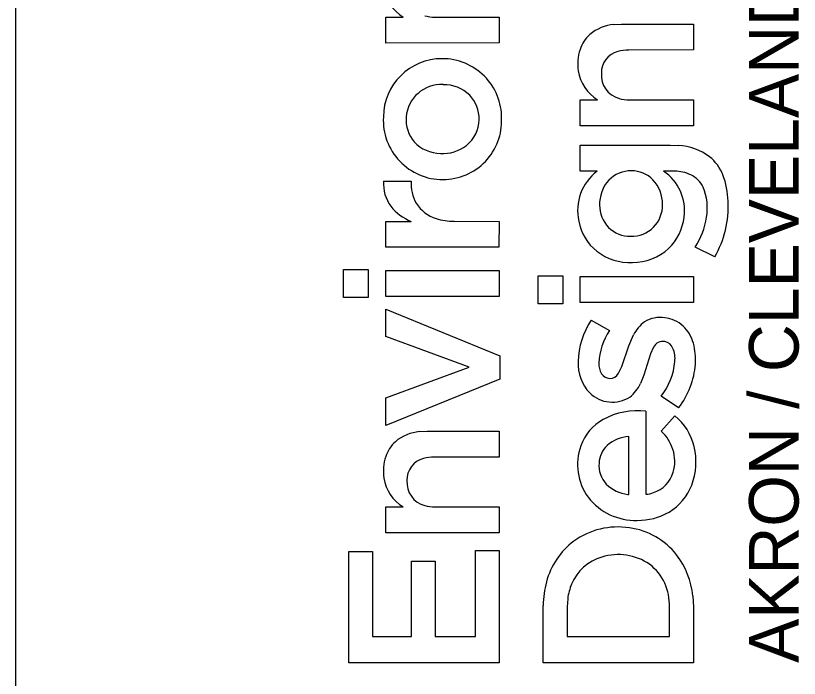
# Model space of a CAD drawing. Extents: x -0.2 to 34, y 0 to 22.
# Drawn here: x 32 to 32.901, y 3.12 to 3.882 of the extents above; entities that cross this region are included whole.
import ezdxf

# ---------------------------------------------------------------- set-up
doc = ezdxf.new("R2010")
doc.units = 0
doc.layers.add('DV_X_Property_Line', color=7, linetype='Continuous')
doc.layers.add('RW_X_Esmt_SH', color=7, linetype='Continuous')

msp = doc.modelspace()

# ---------------------------------------------------------------- linework, layer by layer
at = {"layer": 'DV_X_Property_Line'}
msp.add_line((32, 0.5), (32, 21.5), dxfattribs=at)
at = {"layer": 'RW_X_Esmt_SH'}
for p, q in [((32.42542, 3.88066), (32.44552, 3.88071)), ((32.42542, 3.85086), (32.42542, 3.88066)), ((32.48222, 3.88071), (32.55569, 3.88071)), ((32.55569, 3.88071), (32.55571, 3.85096)), ((32.68784, 3.8722), (32.69634, 3.87266)), ((32.69634, 3.87266), (32.77916, 3.87266)), ((32.77916, 3.87266), (32.77917, 3.84287)), ((32.55571, 3.85096), (32.42542, 3.85086)), ((32.77917, 3.84287), (32.70485, 3.8428)), ((32.64888, 3.7855), (32.66897, 3.78555)), ((32.64888, 3.75569), (32.64888, 3.7855)), ((32.70568, 3.78555), (32.77915, 3.78555)), ((32.77915, 3.78555), (32.77917, 3.75579)), ((32.77917, 3.75579), (32.64888, 3.75569)), ((32.6489, 3.70336), (32.64889, 3.73322)), ((32.64889, 3.73322), (32.75236, 3.73322)), ((32.75236, 3.73322), (32.76191, 3.73285)), ((32.66836, 3.70336), (32.6489, 3.70336)), ((32.75763, 3.70356), (32.74487, 3.70361)), ((32.42299, 3.69193), (32.45454, 3.69193)), ((32.42542, 3.64577), (32.45473, 3.64579)), ((32.42542, 3.61593), (32.42542, 3.64577)), ((32.50413, 3.64581), (32.55571, 3.64573)), ((32.55571, 3.64573), (32.55565, 3.61593)), ((32.55565, 3.61593), (32.42542, 3.61593)), ((32.8036, 3.60491), (32.7812, 3.61598)), ((32.37705, 3.55818), (32.37705, 3.59026)), ((32.37705, 3.59026), (32.40543, 3.59026)), ((32.40543, 3.59026), (32.40543, 3.55818)), ((32.42542, 3.55942), (32.42542, 3.58928)), ((32.42542, 3.58928), (32.55571, 3.58928)), ((32.55571, 3.58928), (32.55571, 3.55942)), ((32.60051, 3.55111), (32.60051, 3.58319)), ((32.60051, 3.58319), (32.62889, 3.58319)), ((32.62889, 3.58319), (32.62889, 3.55111)), ((32.64888, 3.55234), (32.64888, 3.5822)), ((32.64888, 3.5822), (32.77917, 3.5822)), ((32.77917, 3.5822), (32.77917, 3.55234)), ((32.55571, 3.55942), (32.42542, 3.55942)), ((32.40543, 3.55818), (32.37705, 3.55818)), ((32.62889, 3.55111), (32.60051, 3.55111)), ((32.77917, 3.55234), (32.64888, 3.55234)), ((32.42542, 3.51327), (32.42542, 3.5446)), ((32.42542, 3.5446), (32.5567, 3.4913)), ((32.66151, 3.53207), (32.68268, 3.52025)), ((32.70483, 3.50258), (32.71036, 3.51526)), ((32.52117, 3.47798), (32.42542, 3.51327)), ((32.69675, 3.47868), (32.70483, 3.50258)), ((32.73342, 3.50101), (32.72985, 3.4933)), ((32.5567, 3.4913), (32.5567, 3.46441)), ((32.72985, 3.4933), (32.72213, 3.46882)), ((32.42542, 3.44294), (32.52117, 3.47798)), ((32.69299, 3.47117), (32.69675, 3.47868)), ((32.72213, 3.46882), (32.71822, 3.45921)), ((32.5567, 3.46441), (32.42542, 3.41086)), ((32.42542, 3.41086), (32.42542, 3.44294)), ((32.76214, 3.43141), (32.74198, 3.44469)), ((32.72453, 3.42747), (32.72463, 3.33195)), ((32.74228, 3.40465), (32.75768, 3.422)), ((32.46439, 3.40397), (32.47289, 3.40443)), ((32.47289, 3.40443), (32.55571, 3.40443)), ((32.55571, 3.40443), (32.55571, 3.37465)), ((32.70489, 3.33182), (32.70489, 3.39834)), ((32.55571, 3.37465), (32.4814, 3.37457)), ((32.70361, 3.33165), (32.70489, 3.33182)), ((32.42542, 3.31728), (32.44552, 3.31733)), ((32.42542, 3.28747), (32.42542, 3.31728)), ((32.48222, 3.31733), (32.55569, 3.31733)), ((32.55569, 3.31733), (32.55571, 3.28756)), ((32.55571, 3.28756), (32.42542, 3.28747)), ((32.38298, 3.13791), (32.38298, 3.26598)), ((32.38298, 3.26598), (32.41012, 3.26598)), ((32.41012, 3.26598), (32.41012, 3.16827)), ((32.52857, 3.16827), (32.52857, 3.26722)), ((32.52857, 3.26722), (32.55571, 3.26722)), ((32.55571, 3.26722), (32.55571, 3.13791)), ((32.45503, 3.16827), (32.45503, 3.25488)), ((32.45503, 3.25488), (32.48218, 3.25488)), ((32.48218, 3.25488), (32.48218, 3.16827)), ((32.63465, 3.21178), (32.63407, 3.2023)), ((32.77847, 3.21497), (32.77917, 3.2021)), ((32.60643, 3.13799), (32.60644, 3.204)), ((32.63407, 3.2023), (32.63407, 3.16838)), ((32.75149, 3.16834), (32.75153, 3.20239)), ((32.77917, 3.2021), (32.77917, 3.138)), ((32.41012, 3.16827), (32.45503, 3.16827)), ((32.48218, 3.16827), (32.52857, 3.16827)), ((32.63407, 3.16838), (32.75149, 3.16834)), ((32.55571, 3.13791), (32.38298, 3.13791)), ((32.77917, 3.138), (32.60643, 3.13799))]:
    msp.add_line(p, q, dxfattribs=at)
for points in [[(32.42542, 3.85086), (32.42542, 3.88066), (32.44552, 3.88071)], [(32.48222, 3.88071), (32.55569, 3.88071), (32.55571, 3.85096), (32.42542, 3.85086)], [(32.68784, 3.8722), (32.69634, 3.87266), (32.77916, 3.87266), (32.77917, 3.84287), (32.70485, 3.8428)], [(32.64888, 3.75569), (32.64888, 3.7855), (32.66897, 3.78555)], [(32.70568, 3.78555), (32.77915, 3.78555), (32.77917, 3.75579), (32.64888, 3.75569)], [(32.66836, 3.70336), (32.6489, 3.70336), (32.64889, 3.73322), (32.75236, 3.73322), (32.76191, 3.73285)], [(32.75763, 3.70356), (32.74487, 3.70361)], [(32.42299, 3.69193), (32.45454, 3.69193)], [(32.50413, 3.64581), (32.55571, 3.64573), (32.55565, 3.61593), (32.42542, 3.61593)], [(32.42542, 3.61593), (32.42542, 3.64577), (32.45473, 3.64579)], [(32.8036, 3.60491), (32.7812, 3.61598)], [(32.66151, 3.53207), (32.68268, 3.52025)], [(32.69299, 3.47117), (32.69675, 3.47868), (32.70483, 3.50258), (32.71036, 3.51526)], [(32.73342, 3.50101), (32.72985, 3.4933), (32.72213, 3.46882), (32.71822, 3.45921)], [(32.76214, 3.43141), (32.74198, 3.44469)], [(32.72453, 3.42747), (32.72463, 3.33195)], [(32.74228, 3.40465), (32.75768, 3.422)], [(32.46439, 3.40397), (32.47289, 3.40443), (32.55571, 3.40443), (32.55571, 3.37465), (32.4814, 3.37457)], [(32.70361, 3.33165), (32.70489, 3.33182), (32.70489, 3.39834)], [(32.42542, 3.28747), (32.42542, 3.31728), (32.44552, 3.31733)], [(32.48222, 3.31733), (32.55569, 3.31733), (32.55571, 3.28756), (32.42542, 3.28747)], [(32.77847, 3.21497), (32.77917, 3.2021), (32.77917, 3.138), (32.60643, 3.13799)], [(32.63465, 3.21178), (32.63407, 3.2023), (32.63407, 3.16838), (32.75149, 3.16834), (32.75153, 3.20239)], [(32.60643, 3.13799), (32.60644, 3.204)]]:
    msp.add_lwpolyline(points, dxfattribs=at)
for points in [[(32.37705, 3.55818), (32.37705, 3.59026), (32.40543, 3.59026), (32.40543, 3.55818)], [(32.42542, 3.55942), (32.42542, 3.58928), (32.55571, 3.58928), (32.55571, 3.55942)], [(32.60051, 3.55111), (32.60051, 3.58319), (32.62889, 3.58319), (32.62889, 3.55111)], [(32.64888, 3.55234), (32.64888, 3.5822), (32.77917, 3.5822), (32.77917, 3.55234)], [(32.42542, 3.41086), (32.42542, 3.44294), (32.52117, 3.47798), (32.42542, 3.51327), (32.42542, 3.5446), (32.5567, 3.4913), (32.5567, 3.46441)], [(32.38298, 3.13791), (32.38298, 3.26598), (32.41012, 3.26598), (32.41012, 3.16827), (32.45503, 3.16827), (32.45503, 3.25488), (32.48218, 3.25488), (32.48218, 3.16827), (32.52857, 3.16827), (32.52857, 3.26722), (32.55571, 3.26722), (32.55571, 3.13791)]]:
    msp.add_lwpolyline(points, close=True, dxfattribs=at)
for centre, radius, start, end in [((32.47027, 3.92141), 0.04763, 188.96462, 238.69865), ((32.47027, 3.92141), 0.04763, 188.96462, 238.69865), ((32.48183, 3.92286), 0.04215, 254.08913, 270.52838), ((32.48183, 3.92286), 0.04215, 254.08913, 270.52838), ((32.69216, 3.82251), 0.04988, 94.97056, 130.22484), ((32.69216, 3.82251), 0.04988, 94.97056, 130.22484), ((32.68694, 3.83085), 0.04016, 132.22383, 161.68229), ((32.68694, 3.83085), 0.04016, 132.22383, 161.68229), ((32.70217, 3.82642), 0.05602, 162.27398, 187.79173), ((32.70217, 3.82642), 0.05602, 162.27398, 187.79173), ((32.69828, 3.81689), 0.02498, 103.68683, 182.21395), ((32.69828, 3.81689), 0.02498, 103.68683, 182.21395), ((32.70453, 3.79679), 0.04601, 89.60515, 105.33026), ((32.70453, 3.79679), 0.04601, 89.60515, 105.33026), ((32.49014, 3.76543), 0.0674, 89.84756, 179.64047), ((32.49014, 3.76543), 0.0674, 89.84756, 179.64047), ((32.49057, 3.76474), 0.0681, 359.54009, 90.21138), ((32.49057, 3.76474), 0.0681, 359.54009, 90.21138), ((32.69372, 3.82624), 0.04763, 188.96462, 238.69865), ((32.69372, 3.82624), 0.04763, 188.96462, 238.69865), ((32.7008, 3.81381), 0.02757, 175.58441, 255.13816), ((32.7008, 3.81381), 0.02757, 175.58441, 255.13816), ((32.48923, 3.76263), 0.0404, 87.04809, 175.57259), ((32.48923, 3.76263), 0.0404, 87.04809, 175.57259), ((32.49204, 3.75999), 0.04299, 45.84264, 90.98008), ((32.49204, 3.75999), 0.04299, 45.84264, 90.98008), ((32.49458, 3.76421), 0.03821, 357.88569, 44.15902), ((32.49458, 3.76421), 0.03821, 357.88569, 44.15902), ((32.70529, 3.82769), 0.04215, 254.08913, 270.52838), ((32.70529, 3.82769), 0.04215, 254.08913, 270.52838), ((32.49083, 3.76209), 0.06819, 176.8344, 270.40384), ((32.49083, 3.76209), 0.06819, 176.8344, 270.40384), ((32.48729, 3.7625), 0.03848, 175.15378, 221.14706), ((32.48729, 3.7625), 0.03848, 175.15378, 221.14706), ((32.49123, 3.76139), 0.06749, 270.06243, 2.37759), ((32.49123, 3.76139), 0.06749, 270.06243, 2.37759), ((32.49446, 3.76318), 0.0383, 308.28936, 359.43468), ((32.49446, 3.76318), 0.0383, 308.28936, 359.43468), ((32.48919, 3.76607), 0.04228, 223.09994, 268.80895), ((32.48919, 3.76607), 0.04228, 223.09994, 268.80895), ((32.49096, 3.7679), 0.04418, 266.56515, 308.06078), ((32.49096, 3.7679), 0.04418, 266.56515, 308.06078), ((32.75907, 3.66789), 0.06503, 53.40344, 87.49062), ((32.75907, 3.66789), 0.06503, 53.40344, 87.49062), ((32.76517, 3.68039), 0.05141, 21.60748, 50.5577), ((32.76517, 3.68039), 0.05141, 21.60748, 50.5577), ((32.70292, 3.65813), 0.05692, 127.37482, 192.22468), ((32.70292, 3.65813), 0.05692, 127.37482, 192.22468), ((32.70693, 3.66927), 0.0346, 88.47302, 136.42562), ((32.70693, 3.66927), 0.0346, 88.47302, 136.42562), ((32.70814, 3.66963), 0.03424, 44.27195, 90.47623), ((32.70814, 3.66963), 0.03424, 44.27195, 90.47623), ((32.71421, 3.65829), 0.05472, 352.1125, 55.92295), ((32.71421, 3.65829), 0.05472, 352.1125, 55.92295), ((32.75666, 3.65725), 0.04633, 65.01687, 88.8011), ((32.75666, 3.65725), 0.04633, 65.01687, 88.8011), ((32.7626, 3.67155), 0.03085, 26.26808, 63.80301), ((32.7626, 3.67155), 0.03085, 26.26808, 63.80301), ((32.73069, 3.66714), 0.08835, 1.15143, 21.3627), ((32.73069, 3.66714), 0.08835, 1.15143, 21.3627), ((32.46616, 3.68882), 0.04329, 175.87313, 216.34747), ((32.46616, 3.68882), 0.04329, 175.87313, 216.34747), ((32.50087, 3.68948), 0.04639, 176.9688, 209.60636), ((32.50087, 3.68948), 0.04639, 176.9688, 209.60636), ((32.71141, 3.66602), 0.0401, 137.46739, 182.33237), ((32.71141, 3.66602), 0.0401, 137.46739, 182.33237), ((32.70368, 3.666), 0.03996, 358.57141, 43.53765), ((32.70368, 3.666), 0.03996, 358.57141, 43.53765), ((32.73565, 3.66154), 0.05953, 349.30734, 23.43071), ((32.73565, 3.66154), 0.05953, 349.30734, 23.43071), ((32.70538, 3.66244), 0.11383, 329.6388, 3.25998), ((32.70538, 3.66244), 0.11383, 329.6388, 3.25998), ((32.47466, 3.69716), 0.05511, 218.09809, 248.7907), ((32.47466, 3.69716), 0.05511, 218.09809, 248.7907), ((32.49514, 3.68814), 0.04079, 211.94466, 253.2028), ((32.49514, 3.68814), 0.04079, 211.94466, 253.2028), ((32.70645, 3.6637), 0.03511, 178.88208, 271.08374), ((32.70645, 3.6637), 0.03511, 178.88208, 271.08374), ((32.70818, 3.66404), 0.03546, 268.27882, 1.55016), ((32.70818, 3.66404), 0.03546, 268.27882, 1.55016), ((32.50465, 3.7165), 0.07069, 252.46555, 269.57296), ((32.50465, 3.7165), 0.07069, 252.46555, 269.57296), ((32.70988, 3.65708), 0.05887, 313.74196, 353.8554), ((32.70988, 3.65708), 0.05887, 313.74196, 353.8554), ((32.70738, 3.66334), 0.08771, 327.31495, 351.57478), ((32.70738, 3.66334), 0.08771, 327.31495, 351.57478), ((32.70463, 3.65696), 0.05837, 190.75182, 231.28919), ((32.70463, 3.65696), 0.05837, 190.75182, 231.28919), ((32.70954, 3.65901), 0.06051, 269.6361, 312.70877), ((32.70954, 3.65901), 0.06051, 269.6361, 312.70877), ((32.70632, 3.66112), 0.06269, 232.46061, 272.59022), ((32.70632, 3.66112), 0.06269, 232.46061, 272.59022), ((32.73636, 3.48258), 0.08973, 146.53104, 178.7571), ((32.73636, 3.48258), 0.08973, 146.53104, 178.7571), ((32.7406, 3.5026), 0.03263, 80.17192, 122.51969), ((32.7406, 3.5026), 0.03263, 80.17192, 122.51969), ((32.74278, 3.49824), 0.03667, 47.79344, 84.68918), ((32.74278, 3.49824), 0.03667, 47.79344, 84.68918), ((32.74661, 3.49713), 0.04053, 125.51182, 153.41595), ((32.74661, 3.49713), 0.04053, 125.51182, 153.41595), ((32.73788, 3.4946), 0.04267, 14.9966, 46.20632), ((32.73788, 3.4946), 0.04267, 14.9966, 46.20632), ((32.74519, 3.4789), 0.07495, 146.51121, 176.91007), ((32.74519, 3.4789), 0.07495, 146.51121, 176.91007), ((32.74384, 3.49631), 0.01143, 76.66094, 155.7053), ((32.74384, 3.49631), 0.01143, 76.66094, 155.7053), ((32.74397, 3.49511), 0.01256, 21.5098, 78.52618), ((32.74397, 3.49511), 0.01256, 21.5098, 78.52618), ((32.71044, 3.48674), 0.07121, 355.83062, 15.39138), ((32.71044, 3.48674), 0.07121, 355.83062, 15.39138), ((32.72592, 3.48766), 0.03209, 354.57264, 22.06805), ((32.72592, 3.48766), 0.03209, 354.57264, 22.06805), ((32.69666, 3.48238), 0.05005, 177.53659, 222.79318), ((32.69666, 3.48238), 0.05005, 177.53659, 222.79318), ((32.6931, 3.48233), 0.02276, 178.47474, 211.08679), ((32.6931, 3.48233), 0.02276, 178.47474, 211.08679), ((32.68248, 3.49149), 0.0757, 321.81101, 354.79685), ((32.68248, 3.49149), 0.0757, 321.81101, 354.79685), ((32.68952, 3.4882), 0.09219, 321.9777, 355.87384), ((32.68952, 3.4882), 0.09219, 321.9777, 355.87384), ((32.68331, 3.4767), 0.01148, 212.23676, 268.37769), ((32.68331, 3.4767), 0.01148, 212.23676, 268.37769), ((32.68342, 3.47589), 0.01067, 267.71603, 333.73375), ((32.68342, 3.47589), 0.01067, 267.71603, 333.73375), ((32.68098, 3.4758), 0.04077, 308.08772, 335.98736), ((32.68098, 3.4758), 0.04077, 308.08772, 335.98736), ((32.68599, 3.47535), 0.0375, 225.98539, 302.47965), ((32.68599, 3.47535), 0.0375, 225.98539, 302.47965), ((32.7152, 3.34414), 0.08384, 83.61499, 118.28755), ((32.7152, 3.34414), 0.08384, 83.61499, 118.28755), ((32.70239, 3.36906), 0.05583, 118.83082, 160.62438), ((32.70239, 3.36906), 0.05583, 118.83082, 160.62438), ((32.71744, 3.37167), 0.06443, 13.53365, 51.36148), ((32.71744, 3.37167), 0.06443, 13.53365, 51.36148), ((32.46871, 3.35428), 0.04988, 94.96958, 130.22249), ((32.46871, 3.35428), 0.04988, 94.96958, 130.22249), ((32.70785, 3.35609), 0.04235, 94.00805, 130.88169), ((32.70785, 3.35609), 0.04235, 94.00805, 130.88169), ((32.70378, 3.36556), 0.05486, 19.03571, 45.44059), ((32.70378, 3.36556), 0.05486, 19.03571, 45.44059), ((32.46348, 3.36263), 0.04015, 132.22192, 161.68183), ((32.46348, 3.36263), 0.04015, 132.22192, 161.68183), ((32.71041, 3.36612), 0.06437, 160.52012, 215.78311), ((32.71041, 3.36612), 0.06437, 160.52012, 215.78311), ((32.70048, 3.36628), 0.02985, 132.98507, 177.179), ((32.70048, 3.36628), 0.02985, 132.98507, 177.179), ((32.71069, 3.3697), 0.047, 344.60586, 17.007), ((32.71069, 3.3697), 0.047, 344.60586, 17.007), ((32.70635, 3.36921), 0.07579, 339.3542, 13.37853), ((32.70635, 3.36921), 0.07579, 339.3542, 13.37853), ((32.47872, 3.35819), 0.05601, 162.27355, 187.79185), ((32.47872, 3.35819), 0.05601, 162.27355, 187.79185), ((32.47482, 3.34867), 0.02498, 103.68646, 182.21874), ((32.47482, 3.34867), 0.02498, 103.68646, 182.21874), ((32.48108, 3.32856), 0.04601, 89.60494, 105.3284), ((32.48108, 3.32856), 0.04601, 89.60494, 105.3284), ((32.7017, 3.36503), 0.03115, 175.00126, 223.28301), ((32.7017, 3.36503), 0.03115, 175.00126, 223.28301), ((32.7224, 3.36715), 0.03504, 288.00773, 343.55078), ((32.7224, 3.36715), 0.03504, 288.00773, 343.55078), ((32.47026, 3.35802), 0.04762, 188.96199, 238.70369), ((32.47026, 3.35802), 0.04762, 188.96199, 238.70369), ((32.47735, 3.34558), 0.02756, 175.58538, 255.14386), ((32.47735, 3.34558), 0.02756, 175.58538, 255.14386), ((32.70891, 3.37363), 0.04231, 225.06188, 262.79738), ((32.70891, 3.37363), 0.04231, 225.06188, 262.79738), ((32.71894, 3.3652), 0.0626, 300.94269, 338.73225), ((32.71894, 3.3652), 0.0626, 300.94269, 338.73225), ((32.72474, 3.35216), 0.02021, 269.7003, 294.8711), ((32.72474, 3.35216), 0.02021, 269.7003, 294.8711), ((32.71253, 3.37054), 0.06872, 217.74516, 271.65431), ((32.71253, 3.37054), 0.06872, 217.74516, 271.65431), ((32.48183, 3.35948), 0.04215, 254.09162, 270.52835), ((32.48183, 3.35948), 0.04215, 254.09162, 270.52835), ((32.71549, 3.37241), 0.07056, 269.20477, 300.33412), ((32.71549, 3.37241), 0.07056, 269.20477, 300.33412), ((32.69229, 3.20792), 0.08641, 81.19402, 125.99844), ((32.69229, 3.20792), 0.08641, 81.19402, 125.99844), ((32.69458, 3.21132), 0.08272, 37.85208, 82.40204), ((32.69458, 3.21132), 0.08272, 37.85208, 82.40204), ((32.69387, 3.20893), 0.08654, 127.23621, 165.14796), ((32.69387, 3.20893), 0.08654, 127.23621, 165.14796), ((32.69279, 3.19862), 0.06389, 55.67272, 107.20935), ((32.69279, 3.19862), 0.06389, 55.67272, 107.20935), ((32.68586, 3.20567), 0.09308, 5.73329, 37.30396), ((32.68586, 3.20567), 0.09308, 5.73329, 37.30396), ((32.68893, 3.20782), 0.05398, 106.18808, 157.38609), ((32.68893, 3.20782), 0.05398, 106.18808, 157.38609), ((32.69291, 3.20499), 0.05867, 357.46616, 52.26647), ((32.69291, 3.20499), 0.05867, 357.46616, 52.26647), ((32.71426, 3.20281), 0.10783, 164.7861, 179.37039), ((32.71426, 3.20281), 0.10783, 164.7861, 179.37039), ((32.69829, 3.20389), 0.06412, 157.35705, 172.92755), ((32.69829, 3.20389), 0.06412, 157.35705, 172.92755)]:
    msp.add_arc(centre, radius, start, end, dxfattribs=at)

# ---------------------------------------------------------------- texts
msp.add_text('AKRON / CLEVELAND / COLUMBUS', height=0.056969, rotation=90, dxfattribs=at).set_placement((32.90012, 3.138))

doc.saveas('drawing.dxf')
